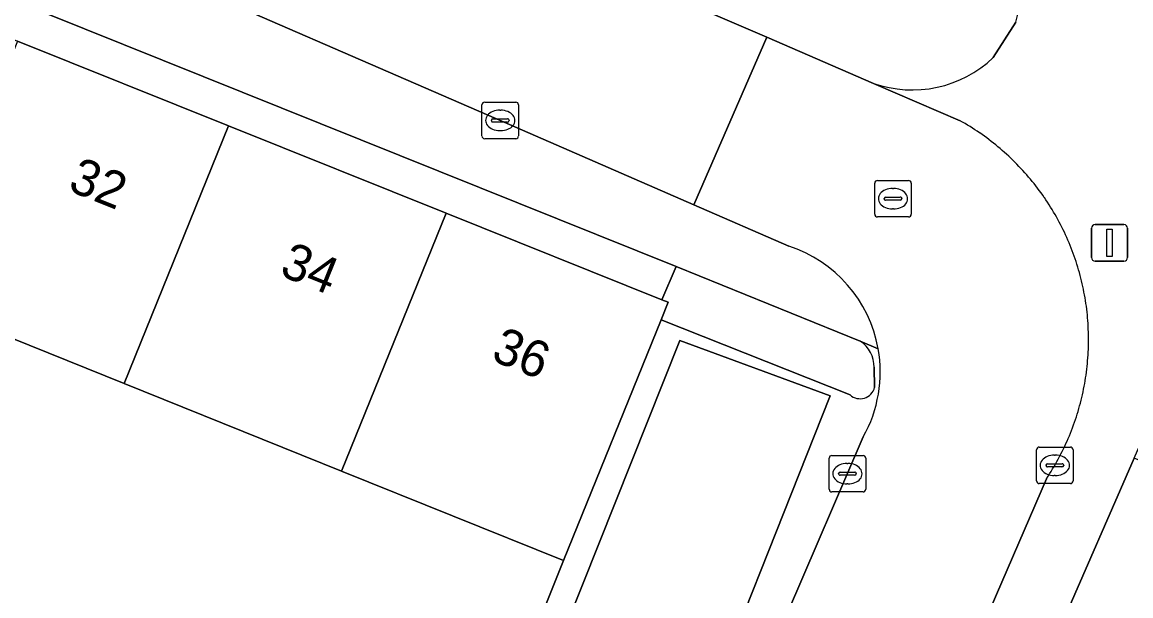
# Model space of a CAD drawing. Extents: x 162803 to 163818, y 381639 to 382475.
# Drawn here: x 163384.58 to 163414.93, y 382060.64 to 382076.36 of the extents above; entities that cross this region are included whole.
import ezdxf

# ---------------------------------------------------------------- set-up
doc = ezdxf.new("R2010")
doc.units = 0
for name, color, linetype in [('IMGEO_Erf', 7, 'Continuous'), ('IMGEO_Groenvoorziening', 7, 'Continuous'), ('IMGEO_Kolk', 7, 'Continuous'), ('IMGEO_Lichtmast', 7, 'Continuous'), ('IMGEO_Pand', 7, 'Continuous'), ('IMGEO_Pand_nummerreeks', 7, 'Continuous'), ('IMGEO_Parkeervlak_open', 7, 'Continuous'), ('IMGEO_Rijbaan_lokaal_open', 7, 'Continuous'), ('IMGEO_Rioolput', 7, 'Continuous'), ('IMGEO_Voetpad_open', 7, 'Continuous')]:
    doc.layers.add(name, color=color, linetype=linetype)

msp = doc.modelspace()

# ---------------------------------------------------------------- linework, layer by layer
at = {"layer": 'IMGEO_Erf'}
msp.add_lwpolyline([(163402.485, 382069.666), (163367.901, 382083.568), (163367.528, 382082.633), (163373.459, 382080.252), (163378.894, 382078.069), (163384.45, 382075.839), (163390.232, 382073.517), (163396.185, 382071.127), (163402.09, 382068.756)], close=True, dxfattribs=at)
msp.add_lwpolyline([(163382.405, 382041.336), (163384.738, 382046.722), (163387.364, 382052.785), (163386.025, 382053.376), (163386.715, 382054.975), (163387.851, 382054.478), (163390.208, 382060.299), (163391.58, 382059.744), (163392.899, 382059.21), (163391.782, 382056.45), (163396.442, 382054.564), (163395.203, 382051.502), (163399.406, 382049.623), (163401.138, 382053.608), (163396.923, 382055.3), (163397.842, 382057.701), (163399.402, 382061.61), (163393.326, 382064.06), (163387.376, 382066.46), (163381.598, 382068.79)], dxfattribs=at)
at = {"layer": 'IMGEO_Groenvoorziening'}
for points in [[(163410.25, 382079.704), (163388.741, 382088.317), (163386.793, 382083.85), (163387.187, 382083.678), (163389.423, 382082.703), (163399.969, 382078.104), (163404.967, 382075.943), (163407.886, 382074.681)], [(163411.165, 382075.387), (163411.783, 382076.357)]]:
    msp.add_lwpolyline(points, dxfattribs=at)
msp.add_lwpolyline([(163425.697, 382054.699), (163433.421, 382051.571), (163438.716, 382049.427), (163440.6, 382054.08), (163415.018, 382064.418), (163413.022, 382059.832), (163423.221, 382055.702)], close=True, dxfattribs=at)
for centre, radius, start, end in [((163409.049, 382077.129), 2.841, 344.232, 64.9856), ((163408.947, 382077.719), 3.218, 250.7374, 313.5643)]:
    msp.add_arc(centre, radius, start, end, dxfattribs=at)
at = {"layer": 'IMGEO_Kolk'}
for p, q in [((163397.168, 382073.239), (163397.168, 382074.091)), ((163397.243, 382074.165), (163398.095, 382074.165)), ((163397.656, 382073.945), (163397.681, 382073.945)), ((163398.169, 382074.091), (163398.169, 382073.239)), ((163397.427, 382073.659), (163397.427, 382073.671)), ((163397.47, 382073.708), (163397.868, 382073.708)), ((163397.911, 382073.671), (163397.911, 382073.659)), ((163397.865, 382073.622), (163397.467, 382073.622)), ((163397.679, 382073.385), (163397.654, 382073.385)), ((163398.095, 382073.165), (163397.243, 382073.165)), ((163412.349, 382063.793), (163412.349, 382064.645)), ((163412.424, 382064.719), (163413.276, 382064.719)), ((163413.35, 382064.645), (163413.35, 382063.793)), ((163406.672, 382063.563), (163406.672, 382064.415)), ((163406.747, 382064.489), (163407.599, 382064.489)), ((163407.16, 382064.269), (163407.185, 382064.269)), ((163407.673, 382064.415), (163407.673, 382063.563)), ((163412.608, 382064.213), (163412.608, 382064.225)), ((163412.651, 382064.262), (163413.049, 382064.262)), ((163412.837, 382064.499), (163412.862, 382064.499)), ((163413.092, 382064.225), (163413.092, 382064.213)), ((163406.931, 382063.983), (163406.931, 382063.995)), ((163407.369, 382063.946), (163406.971, 382063.946)), ((163406.974, 382064.032), (163407.372, 382064.032)), ((163407.415, 382063.995), (163407.415, 382063.983)), ((163413.046, 382064.176), (163412.648, 382064.176)), ((163412.86, 382063.939), (163412.835, 382063.939)), ((163407.183, 382063.709), (163407.158, 382063.709)), ((163413.276, 382063.719), (163412.424, 382063.719)), ((163407.599, 382063.489), (163406.747, 382063.489))]:
    msp.add_line(p, q, dxfattribs=at)
for points in [[(163397.168, 382073.239), (163397.168, 382074.091)], [(163397.243, 382074.165), (163398.095, 382074.165)], [(163398.169, 382074.091), (163398.169, 382073.239)], [(163398.095, 382073.165), (163397.243, 382073.165)], [(163412.349, 382063.793), (163412.349, 382064.645)], [(163412.424, 382064.719), (163413.276, 382064.719)], [(163413.35, 382064.645), (163413.35, 382063.793)], [(163406.672, 382063.563), (163406.672, 382064.415)], [(163406.747, 382064.489), (163407.599, 382064.489)], [(163407.673, 382064.415), (163407.673, 382063.563)], [(163413.276, 382063.719), (163412.424, 382063.719)], [(163407.599, 382063.489), (163406.747, 382063.489)]]:
    msp.add_lwpolyline(points, dxfattribs=at)
for centre, radius, start, end in [((163397.245, 382074.089), 0.0765, 91.552, 178.448), ((163397.245, 382074.089), 0.0765, 91.552, 178.448), ((163398.093, 382074.089), 0.0765, 1.552, 88.448), ((163398.093, 382074.089), 0.0765, 1.552, 88.448), ((163397.467, 382073.668), 0.0403, 85.8775, 175.7526), ((163397.464, 382073.658), 0.0366, 178.938, 274.7102), ((163397.868, 382073.665), 0.043, 264.8664, 352.4533), ((163397.872, 382073.67), 0.0386, 1.7309, 96.639), ((163397.245, 382073.241), 0.0765, 181.552, 268.448), ((163397.245, 382073.241), 0.0765, 181.552, 268.448), ((163398.093, 382073.241), 0.0765, 271.552, 358.448), ((163398.093, 382073.241), 0.0765, 271.552, 358.448), ((163412.426, 382064.643), 0.0765, 91.552, 178.448), ((163412.426, 382064.643), 0.0765, 91.552, 178.448), ((163413.274, 382064.643), 0.0765, 1.552, 88.448), ((163413.274, 382064.643), 0.0765, 1.552, 88.448), ((163406.749, 382064.413), 0.0765, 91.552, 178.448), ((163406.749, 382064.413), 0.0765, 91.552, 178.448), ((163407.597, 382064.413), 0.0765, 1.552, 88.448), ((163407.597, 382064.413), 0.0765, 1.552, 88.448), ((163412.648, 382064.222), 0.0403, 85.8775, 175.7526), ((163413.053, 382064.224), 0.0386, 1.7309, 96.639), ((163406.971, 382063.992), 0.0403, 85.8775, 175.7526), ((163406.968, 382063.982), 0.0366, 178.938, 274.7102), ((163407.372, 382063.989), 0.043, 264.8664, 352.4533), ((163407.376, 382063.994), 0.0386, 1.7309, 96.639), ((163412.645, 382064.212), 0.0366, 178.938, 274.7102), ((163413.049, 382064.219), 0.043, 264.8664, 352.4533), ((163412.426, 382063.795), 0.0765, 181.552, 268.448), ((163412.426, 382063.795), 0.0765, 181.552, 268.448), ((163413.274, 382063.795), 0.0765, 271.552, 358.448), ((163413.274, 382063.795), 0.0765, 271.552, 358.448), ((163406.749, 382063.565), 0.0765, 181.552, 268.448), ((163406.749, 382063.565), 0.0765, 181.552, 268.448), ((163407.597, 382063.565), 0.0765, 271.552, 358.448), ((163407.597, 382063.565), 0.0765, 271.552, 358.448)]:
    msp.add_arc(centre, radius, start, end, dxfattribs=at)
for centre, major_axis, ratio, start_param, end_param in [((163397.655, 382073.665), (-0.387, 0.002), 0.722429, 4.712389, 7.853982), ((163397.68, 382073.665), (-0.39, 0.002), 0.717154, 1.570796, 4.712389), ((163407.159, 382063.989), (-0.387, 0.002), 0.722429, 4.712389, 7.853982), ((163407.184, 382063.989), (-0.39, 0.002), 0.717154, 1.570796, 4.712389), ((163412.836, 382064.219), (-0.387, 0.002), 0.722429, 4.712389, 7.853982), ((163412.861, 382064.219), (-0.39, 0.002), 0.717154, 1.570796, 4.712389)]:
    msp.add_ellipse(centre, major_axis=major_axis, ratio=ratio, start_param=start_param, end_param=end_param, dxfattribs=at)
at = {"layer": 'IMGEO_Lichtmast'}
for p, q in [((163413.852, 382069.912), (163413.852, 382070.712)), ((163413.852, 382070.712), (163413.852, 382069.912)), ((163413.952, 382070.812), (163414.742, 382070.812)), ((163414.742, 382070.812), (163413.952, 382070.812)), ((163414.842, 382070.712), (163414.842, 382069.912)), ((163414.842, 382069.912), (163414.842, 382070.712)), ((163414.742, 382069.812), (163413.952, 382069.812)), ((163413.952, 382069.812), (163414.742, 382069.812))]:
    msp.add_line(p, q, dxfattribs=at)
msp.add_lwpolyline([(163414.272, 382070.687), (163414.422, 382070.687), (163414.422, 382069.937), (163414.272, 382069.937), (163414.272, 382070.687)], dxfattribs=at)
for centre, start, end in [((163413.952, 382070.712), 90, 180), ((163413.952, 382070.712), 90, 180), ((163414.742, 382070.712), 0, 90), ((163414.742, 382070.712), 360, 90), ((163413.952, 382069.912), 180, 270), ((163413.952, 382069.912), 180, 270), ((163414.742, 382069.912), 270, 0), ((163414.742, 382069.912), 270, 0)]:
    msp.add_arc(centre, 0.1, start, end, dxfattribs=at)
at = {"layer": 'IMGEO_Pand'}
for points in [[(163381.598, 382068.79), (163387.376, 382066.46), (163390.232, 382073.517), (163384.45, 382075.839)], [(163387.376, 382066.46), (163393.326, 382064.06), (163396.185, 382071.127), (163390.232, 382073.517)], [(163393.326, 382064.06), (163399.402, 382061.61), (163402.07, 382068.2), (163402.266, 382068.685), (163402.09, 382068.756), (163396.185, 382071.127)]]:
    msp.add_lwpolyline(points, close=True, dxfattribs=at)
at = {"layer": 'IMGEO_Parkeervlak_open'}
msp.add_lwpolyline([(163402.673, 382055.973), (163406.698, 382066.12), (163402.587, 382067.641), (163398.596, 382057.625)], close=True, dxfattribs=at)
at = {"layer": 'IMGEO_Rijbaan_lokaal_open'}
msp.add_lwpolyline([(163404.967, 382075.943), (163399.969, 382078.104), (163389.423, 382082.703), (163387.43, 382078.121), (163397.562, 382073.713), (163402.971, 382071.355)], close=True, dxfattribs=at)
for points in [[(163410.258, 382073.655), (163407.886, 382074.681), (163404.967, 382075.943), (163402.971, 382071.355), (163405.566, 382070.224)], [(163407.605, 382064.998), (163403.46, 382055.36), (163402.476, 382053.071), (163396.542, 382039.272), (163396.293, 382038.699), (163399.219, 382037.435), (163399.546, 382038.215)], [(163406.948, 382050.713), (163412.621, 382063.852)]]:
    msp.add_lwpolyline(points, dxfattribs=at)
for centre, radius, start, end in [((163406.906, 382067.669), 6.861, 55.5033, 60.7564), ((163406.854, 382067.596), 6.95, 50.3027, 55.4832), ((163407.021, 382067.792), 6.692, 44.9458, 50.3353), ((163406.812, 382067.574), 6.995, 39.8456, 44.9961), ((163406.664, 382067.476), 7.171, 34.6668, 39.6926), ((163406.908, 382067.669), 6.861, 29.2436, 34.4967), ((163407.228, 382067.826), 6.505, 23.8763, 29.4168), ((163407.107, 382067.735), 6.652, 18.7547, 24.1711), ((163404.442, 382066.773), 3.629, 10.1588, 71.9673), ((163406.515, 382067.55), 7.273, 13.6803, 18.636), ((163407.208, 382067.722), 6.558, 8.149, 13.6495), ((163407.203, 382067.681), 6.57, 3.0157, 8.4963), ((163406.7, 382067.668), 7.072, 357.8155, 2.9132), ((163404.443, 382066.777), 3.628, 330.6353, 10.0939), ((163406.718, 382067.667), 7.054, 352.7032, 357.8149), ((163406.694, 382067.699), 7.082, 347.3795, 352.4673), ((163406.987, 382067.639), 6.783, 342.0261, 347.3357), ((163407.104, 382067.577), 6.652, 336.81, 342.2272), ((163406.452, 382067.883), 7.372, 331.7241, 336.6127), ((163406.686, 382067.787), 7.121, 326.4586, 331.5201)]:
    msp.add_arc(centre, radius, start, end, dxfattribs=at)
at = {"layer": 'IMGEO_Rioolput'}
for p, q in [((163407.919, 382071.095), (163407.919, 382071.947)), ((163407.994, 382072.021), (163408.846, 382072.021)), ((163408.92, 382071.947), (163408.92, 382071.095)), ((163408.178, 382071.515), (163408.178, 382071.527)), ((163408.221, 382071.564), (163408.619, 382071.564)), ((163408.407, 382071.801), (163408.432, 382071.801)), ((163408.662, 382071.527), (163408.662, 382071.515)), ((163408.616, 382071.478), (163408.218, 382071.478)), ((163408.43, 382071.241), (163408.405, 382071.241)), ((163408.846, 382071.021), (163407.994, 382071.021))]:
    msp.add_line(p, q, dxfattribs=at)
for points in [[(163407.919, 382071.095), (163407.919, 382071.947)], [(163407.994, 382072.021), (163408.846, 382072.021)], [(163408.92, 382071.947), (163408.92, 382071.095)], [(163408.846, 382071.021), (163407.994, 382071.021)]]:
    msp.add_lwpolyline(points, dxfattribs=at)
for centre, radius, start, end in [((163407.996, 382071.945), 0.0765, 91.552, 178.448), ((163407.996, 382071.945), 0.0765, 91.552, 178.448), ((163408.844, 382071.945), 0.0765, 1.552, 88.448), ((163408.844, 382071.945), 0.0765, 1.552, 88.448), ((163408.218, 382071.524), 0.0403, 85.8775, 175.7526), ((163408.215, 382071.514), 0.0366, 178.938, 274.7102), ((163408.619, 382071.521), 0.043, 264.8664, 352.4533), ((163408.623, 382071.526), 0.0386, 1.7309, 96.639), ((163407.996, 382071.097), 0.0765, 181.552, 268.448), ((163407.996, 382071.097), 0.0765, 181.552, 268.448), ((163408.844, 382071.097), 0.0765, 271.552, 358.448), ((163408.844, 382071.097), 0.0765, 271.552, 358.448)]:
    msp.add_arc(centre, radius, start, end, dxfattribs=at)
for centre, major_axis, ratio, start_param, end_param in [((163408.406, 382071.521), (-0.387, 0.002), 0.722429, 4.712389, 7.853982), ((163408.431, 382071.521), (-0.39, 0.002), 0.717154, 1.570796, 4.712389)]:
    msp.add_ellipse(centre, major_axis=major_axis, ratio=ratio, start_param=start_param, end_param=end_param, dxfattribs=at)
at = {"layer": 'IMGEO_Voetpad_open'}
for points in [[(163373.559, 382084.112), (163368.125, 382086.514), (163367.771, 382086.67), (163366.615, 382084.122), (163367.901, 382083.568), (163402.485, 382069.666), (163407.524, 382067.623), (163408.015, 382067.413)], [(163405.566, 382070.224), (163402.971, 382071.355), (163397.562, 382073.713), (163387.43, 382078.121), (163385.192, 382079.095), (163373.559, 382084.112)], [(163411.783, 382076.357), (163411.165, 382075.387)], [(163407.094, 382046.208), (163408.416, 382049.247), (163413.022, 382059.832), (163415.018, 382064.418), (163416.08, 382066.846), (163419.922, 382075.685)], [(163407.886, 382074.681), (163410.258, 382073.655)], [(163407.524, 382067.623), (163402.485, 382069.666), (163402.09, 382068.756), (163402.266, 382068.685), (163402.07, 382068.2), (163407.246, 382066.149)], [(163407.246, 382066.149), (163402.07, 382068.2), (163399.402, 382061.61), (163397.842, 382057.701), (163403.46, 382055.36), (163407.605, 382064.998)], [(163408.015, 382067.413), (163407.524, 382067.623)], [(163407.917, 382066.351), (163407.905, 382066.905)], [(163407.905, 382066.905), (163407.917, 382066.351)], [(163412.621, 382063.852), (163406.948, 382050.713)]]:
    msp.add_lwpolyline(points, dxfattribs=at)
msp.add_lwpolyline([(163402.673, 382055.973), (163398.596, 382057.625), (163402.587, 382067.641), (163406.698, 382066.12)], close=True, dxfattribs=at)
for centre, radius, start, end in [((163409.049, 382077.129), 2.841, 344.232, 64.9856), ((163408.947, 382077.719), 3.218, 250.7374, 313.5643), ((163406.906, 382067.669), 6.861, 55.5033, 60.7564), ((163406.854, 382067.596), 6.95, 50.3027, 55.4832), ((163407.021, 382067.792), 6.692, 44.9458, 50.3353), ((163406.812, 382067.574), 6.995, 39.8456, 44.9961), ((163406.664, 382067.476), 7.171, 34.6668, 39.6926), ((163406.908, 382067.669), 6.861, 29.2436, 34.4967), ((163407.228, 382067.826), 6.505, 23.8763, 29.4168), ((163407.107, 382067.735), 6.652, 18.7547, 24.1711), ((163404.442, 382066.773), 3.629, 10.1588, 71.9673), ((163406.515, 382067.55), 7.273, 13.6803, 18.636), ((163407.208, 382067.722), 6.558, 8.149, 13.6495), ((163407.203, 382067.681), 6.57, 3.0157, 8.4963), ((163406.7, 382067.668), 7.072, 357.8155, 2.9132), ((163407.031, 382066.901), 0.874, 0.2508, 55.6537), ((163407.031, 382066.901), 0.874, 0.2508, 55.6537), ((163404.443, 382066.777), 3.628, 330.6353, 10.0939), ((163406.718, 382067.667), 7.054, 352.7032, 357.8149), ((163406.694, 382067.699), 7.082, 347.3795, 352.4673), ((163407.521, 382066.451), 0.408, 227.6851, 345.823), ((163407.521, 382066.451), 0.408, 227.6851, 345.823), ((163406.987, 382067.639), 6.783, 342.0261, 347.3357), ((163407.104, 382067.577), 6.652, 336.81, 342.2272), ((163406.452, 382067.883), 7.372, 331.7241, 336.6127), ((163406.686, 382067.787), 7.121, 326.4586, 331.5201)]:
    msp.add_arc(centre, radius, start, end, dxfattribs=at)

# ---------------------------------------------------------------- texts
at = {"layer": 'IMGEO_Pand_nummerreeks'}
for s, p in [('32', (163385.8, 382071.761)), ('34', (163391.593, 382069.436)), ('36', (163397.383, 382067.111))]:
    msp.add_text(s, height=1, rotation=338.1236, dxfattribs=at).set_placement(p)

doc.saveas('drawing.dxf')
